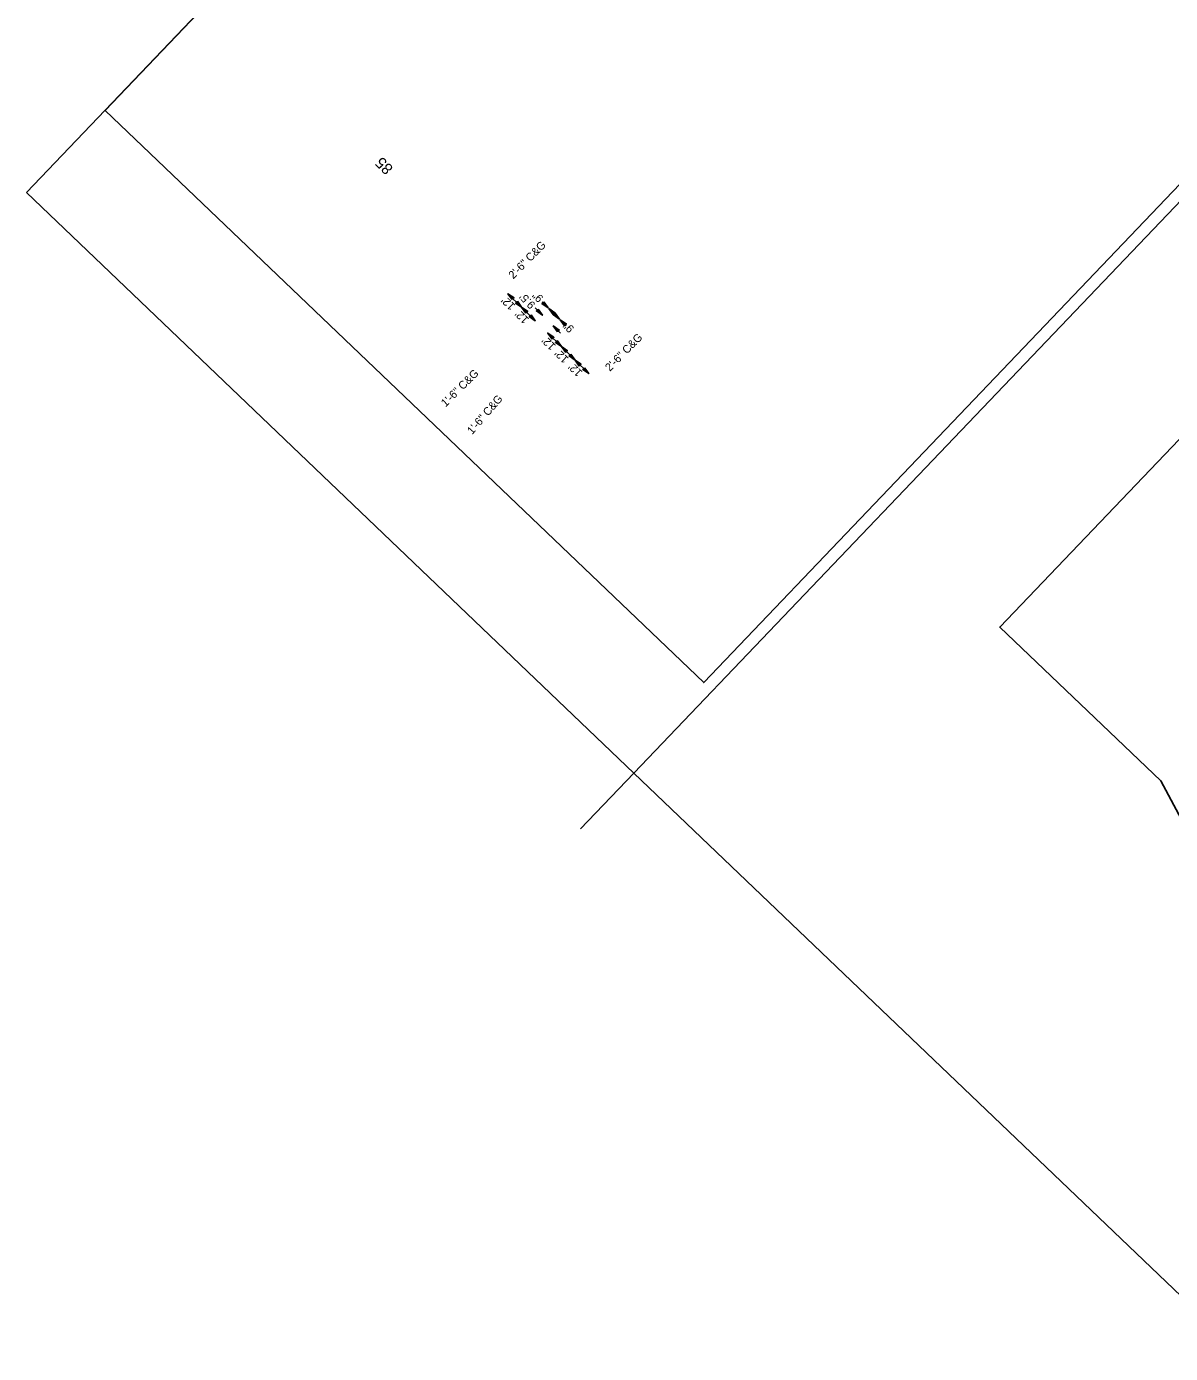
# Model space of a CAD drawing. Extents: x 2326836 to 2328631, y 602012 to 603789.
# Drawn here: x 2326836 to 2327551, y 602012 to 602841 of the extents above; entities that cross this region are included whole.
import ezdxf

# ---------------------------------------------------------------- set-up
doc = ezdxf.new("R2010")
doc.units = 0
for name, color, linetype in [('Old_Level_2', 7, 'Continuous'), ('Prop Dimension', 7, 'Continuous'), ('Prop Dimension Text', 7, 'Continuous'), ('Prop Horizontal Alignment Tick Label', 7, 'Continuous'), ('Prop Terminator CELL', 7, 'Continuous'), ('Scratch_Level_1', 7, 'Continuous'), ('Sheet Plan CELL', 7, 'Continuous')]:
    doc.layers.add(name, color=color, linetype=linetype)

msp = doc.modelspace()

# ---------------------------------------------------------------- linework, layer by layer
at = {"layer": 'Old_Level_2'}
msp.add_line((2327215.55, 602374.93), (2327182.22, 602340.06), dxfattribs=at)
at = {"layer": 'Prop Dimension'}
for p, q in [((2327136.88, 602674.41), (2327145.41, 602665.96)), ((2327158.17, 602669.25), (2327161.9, 602665.58)), ((2327145.41, 602665.96), (2327153.94, 602657.52)), ((2327153.79, 602665.54), (2327158.41, 602660.98)), ((2327162.43, 602665.05), (2327166.16, 602661.37)), ((2327165.33, 602662.2), (2327169.06, 602658.52)), ((2327161.76, 602649.78), (2327170.28, 602641.34)), ((2327165.17, 602654.3), (2327169.8, 602649.73)), ((2327169.59, 602657.99), (2327173.32, 602654.32)), ((2327170.28, 602641.34), (2327178.81, 602632.89)), ((2327178.81, 602632.89), (2327187.34, 602624.45))]:
    msp.add_line(p, q, dxfattribs=at)
at = {"layer": 'Prop Terminator CELL'}
for points in [[(2327139.54, 602670.69), (2327136.88, 602674.41), (2327140.66, 602671.79), (2327139.69, 602671.63)], [(2327142.76, 602669.68), (2327145.41, 602665.96), (2327141.63, 602668.58), (2327142.61, 602668.74)], [(2327159.24, 602669.29), (2327161.9, 602665.58), (2327158.12, 602668.19), (2327159.09, 602668.35)], [(2327148.07, 602662.25), (2327145.41, 602665.96), (2327149.19, 602663.35), (2327148.22, 602663.18)], [(2327151.29, 602661.24), (2327153.94, 602657.52), (2327150.16, 602660.13), (2327151.13, 602660.3)], [(2327155.76, 602664.69), (2327158.41, 602660.98), (2327154.63, 602663.59), (2327155.6, 602663.75)], [(2327165.09, 602661.34), (2327162.43, 602665.05), (2327166.22, 602662.44), (2327165.25, 602662.28)], [(2327166.4, 602662.23), (2327169.06, 602658.52), (2327165.27, 602661.13), (2327166.25, 602661.29)], [(2327164.41, 602646.06), (2327161.76, 602649.78), (2327165.54, 602647.17), (2327164.56, 602647)], [(2327167.83, 602650.59), (2327165.17, 602654.3), (2327168.95, 602651.69), (2327167.98, 602651.52)], [(2327172.25, 602654.28), (2327169.59, 602657.99), (2327173.38, 602655.39), (2327172.4, 602655.22)], [(2327167.63, 602645.05), (2327170.28, 602641.34), (2327166.51, 602643.95), (2327167.48, 602644.12)], [(2327172.94, 602637.62), (2327170.28, 602641.34), (2327174.06, 602638.72), (2327173.09, 602638.56)], [(2327176.16, 602636.61), (2327178.81, 602632.89), (2327175.03, 602635.51), (2327176.01, 602635.67)], [(2327181.46, 602629.18), (2327178.81, 602632.89), (2327182.59, 602630.28), (2327181.62, 602630.12)], [(2327184.69, 602628.17), (2327187.34, 602624.45), (2327183.56, 602627.07), (2327184.53, 602627.23)]]:
    msp.add_lwpolyline(points, close=True, dxfattribs=at)
at = {"layer": 'Scratch_Level_1'}
for points in [[(2326885.09, 602788.9), (2327620.52, 603558.61), (2327714.85, 603468.48), (2327770.17, 603526.38), (2328049.95, 603259.07), (2327259.2, 602431.46)], [(2327580.26, 602303.85), (2327544.86, 602369.97), (2327444.27, 602466.08), (2328040.24, 603089.84), (2328144.79, 602989.94), (2328212.04, 602956.74), (2328326.33, 602847.54), (2327698.72, 602190.66)]]:
    msp.add_lwpolyline(points, close=True, dxfattribs=at)
at = {"layer": 'Sheet Plan CELL'}
for points in [[(2326835.98, 602737.58), (2327550.28, 603485.23), (2327577.17, 603459.54), (2327678.48, 603565.59), (2327746, 603501.08), (2327828.41, 603587.34), (2327892.92, 603525.71), (2328031.11, 603670.36), (2328251.83, 603459.46), (2327215.55, 602374.93)], [(2327215.55, 602374.93), (2328251.82, 603459.46), (2328631.38, 603096.8), (2327595.1, 602012.27)]]:
    msp.add_lwpolyline(points, close=True, dxfattribs=at)

# ---------------------------------------------------------------- texts
at = {"layer": 'Prop Dimension Text'}
for s, rotation, p in [('2\'-6" C&G', 45.42432, (2327140.2, 602683.24)), ("12'", 135.28628, (2327141.83, 602667.01)), ("9.5'", 133.59097, (2327154.37, 602667.73)), ('9"', 135.40258, (2327159.4, 602671.97)), ("12'", 135.28628, (2327150.35, 602658.56)), ('9"', 135.40258, (2327178.63, 602653.01)), ("12'", 135.28628, (2327167.11, 602641.97)), ('2\'-6" C&G', 45.42432, (2327200.57, 602625.55)), ("12'", 135.28628, (2327175.23, 602633.94)), ('1\'-6" C&G', 44.56646, (2327097.89, 602603.33)), ("12'", 135.28628, (2327183.75, 602625.5)), ('1\'-6" C&G', 49.1648, (2327114.54, 602586.06))]:
    msp.add_text(s, height=5, rotation=rotation, dxfattribs=at).set_placement(p)
at = {"layer": 'Prop Horizontal Alignment Tick Label'}
msp.add_text('85', height=7, rotation=135.28519, dxfattribs=at).set_placement((2327065.56, 602753.05))

doc.saveas('drawing.dxf')
